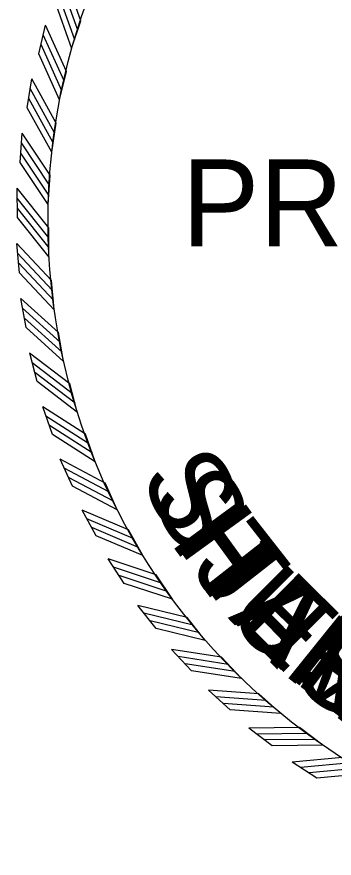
# Model space of a CAD drawing. Extents: x 18 to 14744716, y -5 to 1829144.
# Drawn here: x 17.6804 to 17.7213, y 10.8241 to 10.9324 of the extents above; entities that cross this region are included whole.
import ezdxf

# ---------------------------------------------------------------- set-up
doc = ezdxf.new("R2010")
doc.units = 0
for name, color, linetype in [('B_StampHSS', 7, 'Continuous'), ('B_StampJSB', 7, 'Continuous'), ('B_StampSCR', 7, 'Continuous'), ('B_StampSFH', 7, 'Continuous')]:
    doc.layers.add(name, color=color, linetype=linetype)

msp = doc.modelspace()

# ---------------------------------------------------------------- linework, layer by layer
at = {"layer": 'B_StampHSS'}
for p, q in [((17.6832, 10.92765), (17.68409, 10.93131)), ((17.68744, 10.9283), (17.68864, 10.93188)), ((17.68588, 10.9217), (17.68678, 10.92537)), ((17.68171, 10.9207), (17.68229, 10.92442)), ((17.68487, 10.91499), (17.68546, 10.91873)), ((17.68079, 10.91365), (17.68107, 10.91741)), ((17.68442, 10.90823), (17.68469, 10.912)), ((17.68046, 10.90655), (17.68043, 10.91032)), ((17.68452, 10.90145), (17.68449, 10.90522)), ((17.68072, 10.89945), (17.68037, 10.90321)), ((17.68519, 10.8947), (17.68484, 10.89846)), ((17.68156, 10.8924), (17.68091, 10.89611)), ((17.68641, 10.88803), (17.68575, 10.89175)), ((17.68299, 10.88543), (17.68203, 10.88908)), ((17.68817, 10.88148), (17.68721, 10.88513)), ((17.68498, 10.87861), (17.68372, 10.88217)), ((17.69048, 10.8751), (17.68922, 10.87866)), ((17.68753, 10.87198), (17.68598, 10.87542)), ((17.6933, 10.86893), (17.69175, 10.87238)), ((17.69062, 10.86558), (17.68879, 10.86888)), ((17.69662, 10.86302), (17.69479, 10.86632)), ((17.69422, 10.85945), (17.69213, 10.86259)), ((17.70042, 10.8574), (17.69832, 10.86054)), ((17.69832, 10.85365), (17.69598, 10.8566)), ((17.70466, 10.85211), (17.70232, 10.85507)), ((17.70289, 10.8482), (17.70031, 10.85095)), ((17.70933, 10.8472), (17.70675, 10.84995)), ((17.70789, 10.84315), (17.70509, 10.84568)), ((17.71439, 10.84268), (17.71159, 10.84521)), ((17.71329, 10.83853), (17.71029, 10.84082)), ((17.71981, 10.8386), (17.71681, 10.84089)), ((17.71905, 10.83437), (17.71588, 10.83641))]:
    msp.add_line(p, q, dxfattribs=at)
for points in [[(17.68863, 10.93188), (17.68645, 10.93803)], [(17.68823, 10.93069), (17.68605, 10.93684)], [(17.68784, 10.92944), (17.68566, 10.93559)], [(17.68745, 10.92829), (17.68527, 10.93444)], [(17.68677, 10.92537), (17.68409, 10.93131)], [(17.68646, 10.92415), (17.68378, 10.9301)], [(17.68618, 10.92287), (17.6835, 10.92882)], [(17.68588, 10.92169), (17.6832, 10.92764)], [(17.68545, 10.91872), (17.68229, 10.92443)], [(17.68525, 10.91748), (17.68209, 10.92319)], [(17.68507, 10.91619), (17.68191, 10.92189)], [(17.68487, 10.91499), (17.68171, 10.92069)], [(17.68469, 10.91199), (17.68107, 10.91742)], [(17.68459, 10.91074), (17.68096, 10.91616)], [(17.68452, 10.90943), (17.6809, 10.91486)], [(17.68442, 10.90822), (17.6808, 10.91365)], [(17.68448, 10.90522), (17.68043, 10.91033)], [(17.68448, 10.90396), (17.68043, 10.90907)], [(17.68453, 10.90266), (17.68047, 10.90776)], [(17.68453, 10.90144), (17.68047, 10.90655)], [(17.68484, 10.89846), (17.68037, 10.90321)], [(17.68494, 10.8972), (17.68048, 10.90196)], [(17.68509, 10.8959), (17.68062, 10.90066)], [(17.68519, 10.89469), (17.68072, 10.89945)], [(17.68575, 10.89174), (17.68091, 10.89611)], [(17.68596, 10.8905), (17.68111, 10.89487)], [(17.68621, 10.88922), (17.68137, 10.89359)], [(17.68641, 10.88802), (17.68157, 10.89239)], [(17.68721, 10.88513), (17.68202, 10.88908)], [(17.68752, 10.88391), (17.68233, 10.88786)], [(17.68788, 10.88265), (17.68269, 10.88661)], [(17.68818, 10.88147), (17.68299, 10.88543)], [(17.68922, 10.87866), (17.68372, 10.88217)], [(17.68962, 10.87747), (17.68413, 10.88098)], [(17.69009, 10.87624), (17.68459, 10.87976)], [(17.69048, 10.8751), (17.68498, 10.87861)], [(17.69175, 10.87237), (17.68598, 10.87542)], [(17.69225, 10.87122), (17.68648, 10.87427)], [(17.69282, 10.87004), (17.68705, 10.87309)], [(17.6933, 10.86893), (17.68753, 10.87197)], [(17.69479, 10.86632), (17.68879, 10.86888)], [(17.69539, 10.86521), (17.68939, 10.86777)], [(17.69605, 10.86408), (17.69005, 10.86664)], [(17.69662, 10.86302), (17.69062, 10.86558)], [(17.69832, 10.86054), (17.69213, 10.86259)], [(17.69901, 10.85949), (17.69282, 10.86154)], [(17.69976, 10.85841), (17.69357, 10.86047)], [(17.70042, 10.8574), (17.69423, 10.85945)], [(17.70232, 10.85507), (17.69598, 10.8566)], [(17.70309, 10.85408), (17.69675, 10.85561)], [(17.70392, 10.85307), (17.69758, 10.85461)], [(17.70467, 10.85211), (17.69833, 10.85365)], [(17.70675, 10.84995), (17.70031, 10.85095)], [(17.7076, 10.84902), (17.70116, 10.85003)], [(17.70852, 10.84809), (17.70207, 10.8491)], [(17.70934, 10.84719), (17.7029, 10.8482)], [(17.71159, 10.84521), (17.70509, 10.84568)], [(17.71252, 10.84436), (17.70601, 10.84483)], [(17.71351, 10.8435), (17.707, 10.84397)], [(17.7144, 10.84268), (17.70789, 10.84315)], [(17.71681, 10.84089), (17.71029, 10.84082)], [(17.7178, 10.84012), (17.71128, 10.84005)], [(17.71886, 10.83934), (17.71234, 10.83928)], [(17.71982, 10.8386), (17.71329, 10.83853)], [(17.72237, 10.83701), (17.71587, 10.83641)], [(17.72342, 10.83632), (17.71692, 10.83572)], [(17.72454, 10.83564), (17.71804, 10.83504)], [(17.72555, 10.83498), (17.71906, 10.83437)]]:
    msp.add_lwpolyline(points, dxfattribs=at)
at = {"layer": 'B_StampJSB'}
for p, q in [((17.6832, 10.92765), (17.68409, 10.93131)), ((17.68744, 10.9283), (17.68864, 10.93188)), ((17.68588, 10.9217), (17.68678, 10.92537)), ((17.68171, 10.9207), (17.68229, 10.92442)), ((17.68487, 10.91499), (17.68546, 10.91873)), ((17.68079, 10.91365), (17.68107, 10.91741)), ((17.68442, 10.90823), (17.68469, 10.912)), ((17.68046, 10.90655), (17.68043, 10.91032)), ((17.68452, 10.90145), (17.68449, 10.90522)), ((17.68072, 10.89945), (17.68037, 10.90321)), ((17.68519, 10.8947), (17.68484, 10.89846)), ((17.68156, 10.8924), (17.68091, 10.89611)), ((17.68641, 10.88803), (17.68575, 10.89175)), ((17.68299, 10.88543), (17.68203, 10.88908)), ((17.68817, 10.88148), (17.68721, 10.88513)), ((17.68498, 10.87861), (17.68372, 10.88217)), ((17.69048, 10.8751), (17.68922, 10.87866)), ((17.68753, 10.87198), (17.68598, 10.87542)), ((17.6933, 10.86893), (17.69175, 10.87238)), ((17.69062, 10.86558), (17.68879, 10.86888)), ((17.69662, 10.86302), (17.69479, 10.86632)), ((17.69422, 10.85945), (17.69213, 10.86259)), ((17.70042, 10.8574), (17.69832, 10.86054)), ((17.69832, 10.85365), (17.69598, 10.8566)), ((17.70466, 10.85211), (17.70232, 10.85507)), ((17.70289, 10.8482), (17.70031, 10.85095)), ((17.70933, 10.8472), (17.70675, 10.84995)), ((17.70789, 10.84315), (17.70509, 10.84568)), ((17.71439, 10.84268), (17.71159, 10.84521)), ((17.71329, 10.83853), (17.71029, 10.84082)), ((17.71981, 10.8386), (17.71681, 10.84089)), ((17.71905, 10.83437), (17.71588, 10.83641))]:
    msp.add_line(p, q, dxfattribs=at)
for points in [[(17.68863, 10.93188), (17.68645, 10.93803)], [(17.68823, 10.93069), (17.68605, 10.93684)], [(17.68784, 10.92944), (17.68566, 10.93559)], [(17.68745, 10.92829), (17.68527, 10.93444)], [(17.68677, 10.92537), (17.68409, 10.93131)], [(17.68646, 10.92415), (17.68378, 10.9301)], [(17.68618, 10.92287), (17.6835, 10.92882)], [(17.68588, 10.92169), (17.6832, 10.92764)], [(17.68545, 10.91872), (17.68229, 10.92443)], [(17.68525, 10.91748), (17.68209, 10.92319)], [(17.68507, 10.91619), (17.68191, 10.92189)], [(17.68487, 10.91499), (17.68171, 10.92069)], [(17.68469, 10.91199), (17.68107, 10.91742)], [(17.68459, 10.91074), (17.68096, 10.91616)], [(17.68452, 10.90943), (17.6809, 10.91486)], [(17.68442, 10.90822), (17.6808, 10.91365)], [(17.68448, 10.90522), (17.68043, 10.91033)], [(17.68448, 10.90396), (17.68043, 10.90907)], [(17.68453, 10.90266), (17.68047, 10.90776)], [(17.68453, 10.90144), (17.68047, 10.90655)], [(17.68484, 10.89846), (17.68037, 10.90321)], [(17.68494, 10.8972), (17.68048, 10.90196)], [(17.68509, 10.8959), (17.68062, 10.90066)], [(17.68519, 10.89469), (17.68072, 10.89945)], [(17.68575, 10.89174), (17.68091, 10.89611)], [(17.68596, 10.8905), (17.68111, 10.89487)], [(17.68621, 10.88922), (17.68137, 10.89359)], [(17.68641, 10.88802), (17.68157, 10.89239)], [(17.68721, 10.88513), (17.68202, 10.88908)], [(17.68752, 10.88391), (17.68233, 10.88786)], [(17.68788, 10.88265), (17.68269, 10.88661)], [(17.68818, 10.88147), (17.68299, 10.88543)], [(17.68922, 10.87866), (17.68372, 10.88217)], [(17.68962, 10.87747), (17.68413, 10.88098)], [(17.69009, 10.87624), (17.68459, 10.87976)], [(17.69048, 10.8751), (17.68498, 10.87861)], [(17.69175, 10.87237), (17.68598, 10.87542)], [(17.69225, 10.87122), (17.68648, 10.87427)], [(17.69282, 10.87004), (17.68705, 10.87309)], [(17.6933, 10.86893), (17.68753, 10.87197)], [(17.69479, 10.86632), (17.68879, 10.86888)], [(17.69539, 10.86521), (17.68939, 10.86777)], [(17.69605, 10.86408), (17.69005, 10.86664)], [(17.69662, 10.86302), (17.69062, 10.86558)], [(17.69832, 10.86054), (17.69213, 10.86259)], [(17.69901, 10.85949), (17.69282, 10.86154)], [(17.69976, 10.85841), (17.69357, 10.86047)], [(17.70042, 10.8574), (17.69423, 10.85945)], [(17.70232, 10.85507), (17.69598, 10.8566)], [(17.70309, 10.85408), (17.69675, 10.85561)], [(17.70392, 10.85307), (17.69758, 10.85461)], [(17.70467, 10.85211), (17.69833, 10.85365)], [(17.70675, 10.84995), (17.70031, 10.85095)], [(17.7076, 10.84902), (17.70116, 10.85003)], [(17.70852, 10.84809), (17.70207, 10.8491)], [(17.70934, 10.84719), (17.7029, 10.8482)], [(17.71159, 10.84521), (17.70509, 10.84568)], [(17.71252, 10.84436), (17.70601, 10.84483)], [(17.71351, 10.8435), (17.707, 10.84397)], [(17.7144, 10.84268), (17.70789, 10.84315)], [(17.71681, 10.84089), (17.71029, 10.84082)], [(17.7178, 10.84012), (17.71128, 10.84005)], [(17.71886, 10.83934), (17.71234, 10.83928)], [(17.71982, 10.8386), (17.71329, 10.83853)], [(17.72237, 10.83701), (17.71587, 10.83641)], [(17.72342, 10.83632), (17.71692, 10.83572)], [(17.72454, 10.83564), (17.71804, 10.83504)], [(17.72555, 10.83498), (17.71906, 10.83437)]]:
    msp.add_lwpolyline(points, dxfattribs=at)
msp.add_circle((17.76645, 10.90612), 0.08205, dxfattribs=at)
at = {"layer": 'B_StampSCR'}
for p, q in [((17.6832, 10.92765), (17.68409, 10.93131)), ((17.68744, 10.9283), (17.68864, 10.93188)), ((17.68588, 10.9217), (17.68678, 10.92537)), ((17.68171, 10.9207), (17.68229, 10.92442)), ((17.68487, 10.91499), (17.68546, 10.91873)), ((17.68079, 10.91365), (17.68107, 10.91741)), ((17.68442, 10.90823), (17.68469, 10.912)), ((17.68046, 10.90655), (17.68043, 10.91032)), ((17.68452, 10.90145), (17.68449, 10.90522)), ((17.68072, 10.89945), (17.68037, 10.90321)), ((17.68519, 10.8947), (17.68484, 10.89846)), ((17.68156, 10.8924), (17.68091, 10.89611)), ((17.68641, 10.88803), (17.68575, 10.89175)), ((17.68299, 10.88543), (17.68203, 10.88908)), ((17.68817, 10.88148), (17.68721, 10.88513)), ((17.68498, 10.87861), (17.68372, 10.88217)), ((17.69048, 10.8751), (17.68922, 10.87866)), ((17.68753, 10.87198), (17.68598, 10.87542)), ((17.6933, 10.86893), (17.69175, 10.87238)), ((17.69062, 10.86558), (17.68879, 10.86888)), ((17.69662, 10.86302), (17.69479, 10.86632)), ((17.69422, 10.85945), (17.69213, 10.86259)), ((17.70042, 10.8574), (17.69832, 10.86054)), ((17.69832, 10.85365), (17.69598, 10.8566)), ((17.70466, 10.85211), (17.70232, 10.85507)), ((17.70289, 10.8482), (17.70031, 10.85095)), ((17.70933, 10.8472), (17.70675, 10.84995)), ((17.70789, 10.84315), (17.70509, 10.84568)), ((17.71439, 10.84268), (17.71159, 10.84521)), ((17.71329, 10.83853), (17.71029, 10.84082)), ((17.71981, 10.8386), (17.71681, 10.84089)), ((17.71905, 10.83437), (17.71588, 10.83641))]:
    msp.add_line(p, q, dxfattribs=at)
for points in [[(17.68863, 10.93188), (17.68645, 10.93803)], [(17.68823, 10.93069), (17.68605, 10.93684)], [(17.68784, 10.92944), (17.68566, 10.93559)], [(17.68745, 10.92829), (17.68527, 10.93444)], [(17.68677, 10.92537), (17.68409, 10.93131)], [(17.68646, 10.92415), (17.68378, 10.9301)], [(17.68618, 10.92287), (17.6835, 10.92882)], [(17.68588, 10.92169), (17.6832, 10.92764)], [(17.68545, 10.91872), (17.68229, 10.92443)], [(17.68525, 10.91748), (17.68209, 10.92319)], [(17.68507, 10.91619), (17.68191, 10.92189)], [(17.68487, 10.91499), (17.68171, 10.92069)], [(17.68469, 10.91199), (17.68107, 10.91742)], [(17.68459, 10.91074), (17.68096, 10.91616)], [(17.68452, 10.90943), (17.6809, 10.91486)], [(17.68442, 10.90822), (17.6808, 10.91365)], [(17.68448, 10.90522), (17.68043, 10.91033)], [(17.68448, 10.90396), (17.68043, 10.90907)], [(17.68453, 10.90266), (17.68047, 10.90776)], [(17.68453, 10.90144), (17.68047, 10.90655)], [(17.68484, 10.89846), (17.68037, 10.90321)], [(17.68494, 10.8972), (17.68048, 10.90196)], [(17.68509, 10.8959), (17.68062, 10.90066)], [(17.68519, 10.89469), (17.68072, 10.89945)], [(17.68575, 10.89174), (17.68091, 10.89611)], [(17.68596, 10.8905), (17.68111, 10.89487)], [(17.68621, 10.88922), (17.68137, 10.89359)], [(17.68641, 10.88802), (17.68157, 10.89239)], [(17.68721, 10.88513), (17.68202, 10.88908)], [(17.68752, 10.88391), (17.68233, 10.88786)], [(17.68788, 10.88265), (17.68269, 10.88661)], [(17.68818, 10.88147), (17.68299, 10.88543)], [(17.68922, 10.87866), (17.68372, 10.88217)], [(17.68962, 10.87747), (17.68413, 10.88098)], [(17.69009, 10.87624), (17.68459, 10.87976)], [(17.69048, 10.8751), (17.68498, 10.87861)], [(17.69175, 10.87237), (17.68598, 10.87542)], [(17.69225, 10.87122), (17.68648, 10.87427)], [(17.69282, 10.87004), (17.68705, 10.87309)], [(17.6933, 10.86893), (17.68753, 10.87197)], [(17.69479, 10.86632), (17.68879, 10.86888)], [(17.69539, 10.86521), (17.68939, 10.86777)], [(17.69605, 10.86408), (17.69005, 10.86664)], [(17.69662, 10.86302), (17.69062, 10.86558)], [(17.69832, 10.86054), (17.69213, 10.86259)], [(17.69901, 10.85949), (17.69282, 10.86154)], [(17.69976, 10.85841), (17.69357, 10.86047)], [(17.70042, 10.8574), (17.69423, 10.85945)], [(17.70232, 10.85507), (17.69598, 10.8566)], [(17.70309, 10.85408), (17.69675, 10.85561)], [(17.70392, 10.85307), (17.69758, 10.85461)], [(17.70467, 10.85211), (17.69833, 10.85365)], [(17.70675, 10.84995), (17.70031, 10.85095)], [(17.7076, 10.84902), (17.70116, 10.85003)], [(17.70852, 10.84809), (17.70207, 10.8491)], [(17.70934, 10.84719), (17.7029, 10.8482)], [(17.71159, 10.84521), (17.70509, 10.84568)], [(17.71252, 10.84436), (17.70601, 10.84483)], [(17.71351, 10.8435), (17.707, 10.84397)], [(17.7144, 10.84268), (17.70789, 10.84315)], [(17.71681, 10.84089), (17.71029, 10.84082)], [(17.7178, 10.84012), (17.71128, 10.84005)], [(17.71886, 10.83934), (17.71234, 10.83928)], [(17.71982, 10.8386), (17.71329, 10.83853)], [(17.72237, 10.83701), (17.71587, 10.83641)], [(17.72342, 10.83632), (17.71692, 10.83572)], [(17.72454, 10.83564), (17.71804, 10.83504)], [(17.72555, 10.83498), (17.71906, 10.83437)]]:
    msp.add_lwpolyline(points, dxfattribs=at)
at = {"layer": 'B_StampSFH'}
for p, q in [((17.6832, 10.92765), (17.68409, 10.93131)), ((17.68744, 10.9283), (17.68864, 10.93188)), ((17.68588, 10.9217), (17.68678, 10.92537)), ((17.68171, 10.9207), (17.68229, 10.92442)), ((17.68487, 10.91499), (17.68546, 10.91873)), ((17.68079, 10.91365), (17.68107, 10.91741)), ((17.68442, 10.90823), (17.68469, 10.912)), ((17.68046, 10.90655), (17.68043, 10.91032)), ((17.68452, 10.90145), (17.68449, 10.90522)), ((17.68072, 10.89945), (17.68037, 10.90321)), ((17.68519, 10.8947), (17.68484, 10.89846)), ((17.68156, 10.8924), (17.68091, 10.89611)), ((17.68641, 10.88803), (17.68575, 10.89175)), ((17.68299, 10.88543), (17.68203, 10.88908)), ((17.68817, 10.88148), (17.68721, 10.88513)), ((17.68498, 10.87861), (17.68372, 10.88217)), ((17.69048, 10.8751), (17.68922, 10.87866)), ((17.68753, 10.87198), (17.68598, 10.87542)), ((17.6933, 10.86893), (17.69175, 10.87238)), ((17.69062, 10.86558), (17.68879, 10.86888)), ((17.69662, 10.86302), (17.69479, 10.86632)), ((17.69422, 10.85945), (17.69213, 10.86259)), ((17.70042, 10.8574), (17.69832, 10.86054)), ((17.69832, 10.85365), (17.69598, 10.8566)), ((17.70466, 10.85211), (17.70232, 10.85507)), ((17.70289, 10.8482), (17.70031, 10.85095)), ((17.70933, 10.8472), (17.70675, 10.84995)), ((17.70789, 10.84315), (17.70509, 10.84568)), ((17.71439, 10.84268), (17.71159, 10.84521)), ((17.71329, 10.83853), (17.71029, 10.84082)), ((17.71981, 10.8386), (17.71681, 10.84089)), ((17.71905, 10.83437), (17.71588, 10.83641))]:
    msp.add_line(p, q, dxfattribs=at)
for points in [[(17.68863, 10.93188), (17.68645, 10.93803)], [(17.68823, 10.93069), (17.68605, 10.93684)], [(17.68784, 10.92944), (17.68566, 10.93559)], [(17.68745, 10.92829), (17.68527, 10.93444)], [(17.68677, 10.92537), (17.68409, 10.93131)], [(17.68646, 10.92415), (17.68378, 10.9301)], [(17.68618, 10.92287), (17.6835, 10.92882)], [(17.68588, 10.92169), (17.6832, 10.92764)], [(17.68545, 10.91872), (17.68229, 10.92443)], [(17.68525, 10.91748), (17.68209, 10.92319)], [(17.68507, 10.91619), (17.68191, 10.92189)], [(17.68487, 10.91499), (17.68171, 10.92069)], [(17.68469, 10.91199), (17.68107, 10.91742)], [(17.68459, 10.91074), (17.68096, 10.91616)], [(17.68452, 10.90943), (17.6809, 10.91486)], [(17.68442, 10.90822), (17.6808, 10.91365)], [(17.68448, 10.90522), (17.68043, 10.91033)], [(17.68448, 10.90396), (17.68043, 10.90907)], [(17.68453, 10.90266), (17.68047, 10.90776)], [(17.68453, 10.90144), (17.68047, 10.90655)], [(17.68484, 10.89846), (17.68037, 10.90321)], [(17.68494, 10.8972), (17.68048, 10.90196)], [(17.68509, 10.8959), (17.68062, 10.90066)], [(17.68519, 10.89469), (17.68072, 10.89945)], [(17.68575, 10.89174), (17.68091, 10.89611)], [(17.68596, 10.8905), (17.68111, 10.89487)], [(17.68621, 10.88922), (17.68137, 10.89359)], [(17.68641, 10.88802), (17.68157, 10.89239)], [(17.68721, 10.88513), (17.68202, 10.88908)], [(17.68752, 10.88391), (17.68233, 10.88786)], [(17.68788, 10.88265), (17.68269, 10.88661)], [(17.68818, 10.88147), (17.68299, 10.88543)], [(17.68922, 10.87866), (17.68372, 10.88217)], [(17.68962, 10.87747), (17.68413, 10.88098)], [(17.69009, 10.87624), (17.68459, 10.87976)], [(17.69048, 10.8751), (17.68498, 10.87861)], [(17.69175, 10.87237), (17.68598, 10.87542)], [(17.69225, 10.87122), (17.68648, 10.87427)], [(17.69282, 10.87004), (17.68705, 10.87309)], [(17.6933, 10.86893), (17.68753, 10.87197)], [(17.69479, 10.86632), (17.68879, 10.86888)], [(17.69539, 10.86521), (17.68939, 10.86777)], [(17.69605, 10.86408), (17.69005, 10.86664)], [(17.69662, 10.86302), (17.69062, 10.86558)], [(17.69832, 10.86054), (17.69213, 10.86259)], [(17.69901, 10.85949), (17.69282, 10.86154)], [(17.69976, 10.85841), (17.69357, 10.86047)], [(17.70042, 10.8574), (17.69423, 10.85945)], [(17.70232, 10.85507), (17.69598, 10.8566)], [(17.70309, 10.85408), (17.69675, 10.85561)], [(17.70392, 10.85307), (17.69758, 10.85461)], [(17.70467, 10.85211), (17.69833, 10.85365)], [(17.70675, 10.84995), (17.70031, 10.85095)], [(17.7076, 10.84902), (17.70116, 10.85003)], [(17.70852, 10.84809), (17.70207, 10.8491)], [(17.70934, 10.84719), (17.7029, 10.8482)], [(17.71159, 10.84521), (17.70509, 10.84568)], [(17.71252, 10.84436), (17.70601, 10.84483)], [(17.71351, 10.8435), (17.707, 10.84397)], [(17.7144, 10.84268), (17.70789, 10.84315)], [(17.71681, 10.84089), (17.71029, 10.84082)], [(17.7178, 10.84012), (17.71128, 10.84005)], [(17.71886, 10.83934), (17.71234, 10.83928)], [(17.71982, 10.8386), (17.71329, 10.83853)], [(17.72237, 10.83701), (17.71587, 10.83641)], [(17.72342, 10.83632), (17.71692, 10.83572)], [(17.72454, 10.83564), (17.71804, 10.83504)], [(17.72555, 10.83498), (17.71906, 10.83437)]]:
    msp.add_lwpolyline(points, dxfattribs=at)

# ---------------------------------------------------------------- texts
at = {"layer": 'B_StampHSS'}
msp.add_text('PROFESSIONAL', height=0.0111938, dxfattribs=at).set_placement((17.70165, 10.90284))
for s, rotation, p in [('H', 306.2262, (17.7, 10.86484)), ('U', 314.9716, (17.70705, 10.85522)), ('S', 323.717, (17.71548, 10.84678))]:
    msp.add_text(s, height=0.01042, rotation=rotation, dxfattribs=at).set_placement(p)
at = {"layer": 'B_StampJSB'}
msp.add_text('PROFESSIONAL', height=0.0111938, dxfattribs=at).set_placement((17.70165, 10.90284))
for s, rotation, p in [('J', 308.0032, (17.70263, 10.86129)), ('A', 313.8414, (17.70752, 10.85503)), ('M', 321.1392, (17.71449, 10.84796))]:
    msp.add_text(s, height=0.01042, rotation=rotation, dxfattribs=at).set_placement(p)
at = {"layer": 'B_StampSCR'}
msp.add_text('PROFESSIONAL', height=0.0111938, dxfattribs=at).set_placement((17.70165, 10.90284))
for s, rotation, p in [('S', 298.6097, (17.69604, 10.87315)), ('H', 305.9057, (17.7008, 10.86443)), ('A', 314.6609, (17.70791, 10.85487)), ('R', 321.9569, (17.71489, 10.84781))]:
    msp.add_text(s, height=0.01042, rotation=rotation, dxfattribs=at).set_placement(p)
at = {"layer": 'B_StampSFH'}
msp.add_text('PROFESSIONAL', height=0.0111938, dxfattribs=at).set_placement((17.70165, 10.90284))
for s, rotation, p in [('S', 300.7985, (17.69735, 10.87048)), ('T', 308.0945, (17.70244, 10.86194)), ('E', 315.3905, (17.70857, 10.85413)), ('P', 323.0513, (17.71602, 10.84682))]:
    msp.add_text(s, height=0.01042, rotation=rotation, dxfattribs=at).set_placement(p)

doc.saveas('drawing.dxf')
